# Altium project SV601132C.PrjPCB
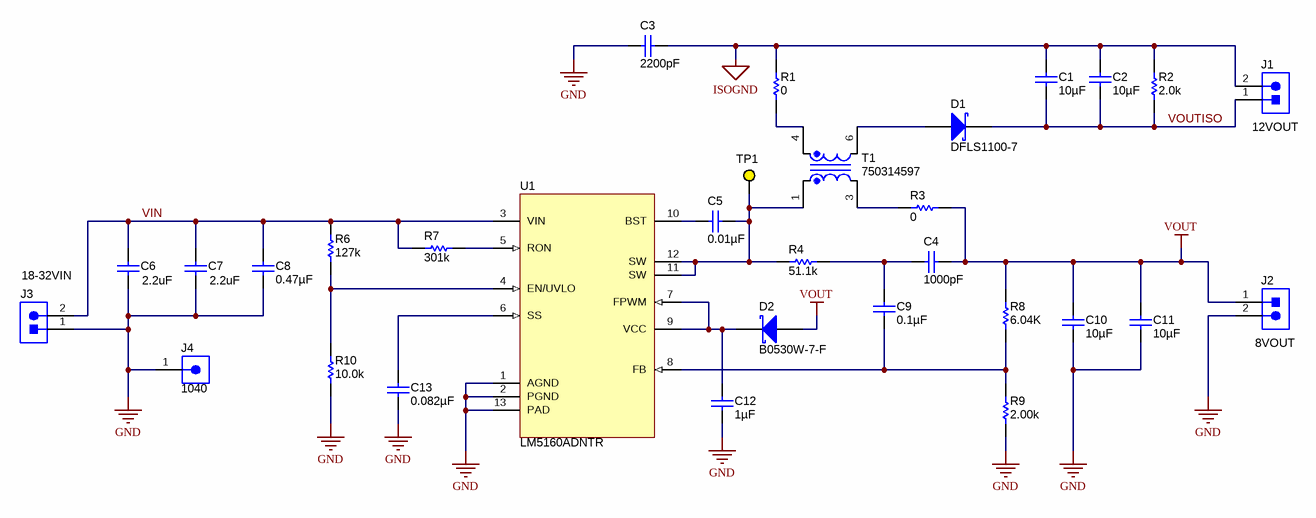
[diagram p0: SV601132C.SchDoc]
CopyrightYear: 2014; PCB_Layout: a0413446; PCB_Rev: B; PRJ_Customer: Public Release; PRJ_Engineer: a0221128; PRJ_Number: SV601132; PRJ_Title: LM5160DNTFBKEVM; SCH_Rev: C; TechSupport: http://www.ti.com/support; TID: N/A
2 sheets, 47 parts. Net scope: global (net labels, ports and power ports of the same name join across sheets).
Board file: SV601132B.PcbDoc
Sheets:
  SV601132C.SchDoc
  SV601132C_HW.SchDoc

## Sheet SV601132C.SchDoc
size 431 x 279 mm; Date: Not shown in title block; ApprovedBy: Not shown in title block; CheckedBy: Not shown in title block; Author: Not shown in title block; CompanyName: Not shown in title block; Engineer: Not shown in title block; Organization: Not shown in title block; Address1: Not shown in title block; Address2: Not shown in title block; Address3: Not shown in title block; Address4: Not shown in title block; DocumentNumber: 1; Revision: Use project parameter SCH_Rev; SheetNumber: 1; SheetTotal: 2; PageSetup: Record=PageOptions¦CenterHorizontal=True¦CenterVertical=True¦PrintScale=0.62¦XCorrection=1.00¦YCorrection=1.00¦PrintKind=0¦BorderSize=5000000¦LeftOffset=0¦BottomOffset=0¦Orientation=2¦PaperLength=1000¦PaperWidth=1000¦Scale=100¦PaperSource=7¦PrintQuality=600¦MediaType=1¦DitherType=10¦PaperKind=Letter¦PrintScaleMode=1

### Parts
C1  ValueDisplayed: 10µF  [1210]  (hidden comment: GRM32ER7YA106KA12L)
C2  ValueDisplayed: 10µF  [1210]  (hidden comment: GRM32ER7YA106KA12L)
C3  ValueDisplayed: 2200pF  [1812]  (hidden comment: C4532X7R3D222K130KA)
C4  ValueDisplayed: 1000pF  [0603]  (hidden comment: GRM188R71C102KA01D)
C5  ValueDisplayed: 0.01µF  [0603]  (hidden comment: GRM188R71C103KA01D)
C6  value 2.2uF  [1210]  (hidden comment: GRM32ER72A225KA35K)
C7  value 2.2uF  [1210]  (hidden comment: GRM32ER72A225KA35K)
C8  ValueDisplayed: 0.47µF  [0805_HV]  (hidden comment: GRM21BR72A474KA73L)
C9  ValueDisplayed: 0.1µF  [0603]  (hidden comment: 06033C104JAT2A)
C10  ValueDisplayed: 10µF  [1210]  (hidden comment: GRM32ER7YA106KA12L)
C11  ValueDisplayed: 10µF  [1210]  (hidden comment: GRM32ER7YA106KA12L)
C12  ValueDisplayed: 1µF  [0603]  (hidden comment: C1608X7R1C105K080AC)
C13  ValueDisplayed: 0.082µF  [0603]  (hidden comment: GRM188R71C823KA01D)
D1  DFLS1100-7  [powerDI123]
D2  B0530W-7-F  [SOD-123]
J1  ED555/2DS  [TERM_BLK_ED555-2DS]  (value not drawn)
J2  ED555/2DS  [TERM_BLK_ED555-2DS]  (value not drawn)
J3  ED555/2DS  [TERM_BLK_ED555-2DS]  (value not drawn)
J4  1040  [CONN_1040]
R1  value 0  [0805_HV]  (hidden comment: CRCW08050000Z0EA)
R2  value 2.0k  [0805_HV]  (hidden comment: CRCW08052K00JNEA)
R3  value 0  [0805_HV]  (hidden comment: CRCW08050000Z0EA)
R4  value 51.1k  [0603]  (hidden comment: RC0603FR-0751K1L)
R6  value 127k  [0603]  (hidden comment: RC0603FR-07127KL)
R7  value 301k  [0603]  (hidden comment: CRCW0603301KFKEA)
R8  value 6.04K  [0603]  (hidden comment: CRCW06036K04FKEA)
R9  value 2.00k  [0603]  (hidden comment: CRCW06032K00FKEA)
R10  value 10.0k  [0603]  (hidden comment: CRCW060310K0FKEA)
T1  750314597  [WURTH_750314597]
TP1  5014  [Keystone5014]  (value not drawn)
U1  LM5160ADNTR  [DNT0012B]

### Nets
GND: C3.1 C6.2 C7.2 C8.2 C10.2 C11.2 C12.2 C13.2 J2.2 J3.1 J4.1 R9.1 R10.1 U1.1(AGND) U1.2(PGND) U1.13(PAD)
ISOGND: C1.1 C2.1 C3.2 J1.2 R1.2 R2.2
VOUT: C4.2 C10.1 C11.1 D2.2(A) J2.1 R3.1 R8.2
VIN: C6.1 C7.1 C8.1 J3.2 R6.2 R7.2 U1.3(VIN)
VOUTISO: C1.2 C2.2 D1.1(K) J1.1 R2.1
NetC4_1: C4.1 C9.1 R4.2
NetC5_1: C5.1 R4.1 T1.1 TP1.1 U1.11(SW) U1.12(SW)
NetC5_2: C5.2 U1.10(BST)
NetC9_2: C9.2 R8.1 R9.2 U1.8(FB)
NetC12_1: C12.1 D2.1(K) U1.7(FPWM) U1.9(VCC)
NetC13_1: C13.1 U1.6(SS)
NetD1_2: D1.2(A) T1.6
NetR1_1: R1.1 T1.4
NetR3_2: R3.2 T1.3
NetR6_1: R6.1 R10.2 U1.4(EN/UVLO)
NetR7_1: R7.1 U1.5(RON)

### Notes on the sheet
- (near J1) 12VOUT
- (near J3) 18-32VIN
- (near J2) 8VOUT

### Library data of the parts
C1 C2 C10 C11 = GRM32ER7YA106KA12L: CAP, CERM, 10uF, 35V, +/-10%, X7R, 1210; Manufacturer: MuRata; Polarized: N; CompType: Capacitor; U/M: EA; Cap_F: 0.00001; Tolerance_%: 10; Value1: Unknown; VDC_V: 35; TaMin_C: -55; TaMax_C: 125
C3 = C4532X7R3D222K: CAP, CERM, 2200pF, 2000V, +/-10%, X7R, 1812; Manufacturer: TDK; Polarized: N; CompType: Capacitor; U/M: EA; Cap_F: 0.0000000022; Tolerance_%: 10; Value1: Unknown; VDC_V: 2000; TaMin_C: -55; TaMax_C: 125
C4 = GRM188R71C102KA01D: CAP, CERM, 1000pF, 16V, +/-10%, X7R, 0603; Manufacturer: MuRata; Polarized: N; CompType: Capacitor; U/M: EA; Cap_F: 0.000000001; Tolerance_%: 10; Value1: Unknown; VDC_V: 16; TaMin_C: -55; TaMax_C: 125
C5 = GRM188R71C103KA01D: CAP, CERM, 0.01uF, 16V, +/-10%, X7R, 0603; Manufacturer: MuRata; Polarized: N; CompType: Capacitor; U/M: EA; Cap_F: 0.00000001; Tolerance_%: 10; Value1: Unknown; VDC_V: 16; TaMin_C: -55; TaMax_C: 125
C6 C7 = Capacitor: CAP, CERM, 2.2uF, 100V, X7R, 10%, 1210; Manufacturer: Murata; Polarized: N; U/M: EA
C8 = GRM21BR72A474KA73L: CAP, CERM, 0.47uF, 100V, +/-10%, X7R, 0805; Manufacturer: MuRata; Polarized: N; CompType: Capacitor; U/M: EA; Cap_F: 0.00000047; Tolerance_%: 10; Value1: Unknown; VDC_V: 100; TaMin_C: -55; TaMax_C: 125; Cap_Case: 0805
C9 = 06033C104JAT2A: CAP, CERM, 0.1uF, 25V, +/-5%, X7R, 0603; Manufacturer: AVX; Polarized: N; CompType: Capacitor; U/M: EA; Cap_F: 0.0000001; Tolerance_%: 5; ESR_Ohm: 0.05; Value1: 0.05 ohm; VDC_V: 25; TaMin_C: -55; TaMax_C: 125
C12 = C1608X7R1C105K080AC: CAP, CERM, 1 µF, 16 V, +/- 10%, X7R, 0603; Manufacturer: TDK; Polarized: N; CompType: Capacitor; Value: 1uF; U/M: EA; Cap_F: 0.000001; Tolerance_%: 10; ESR_ohm: 0.0057; Value1: 0.0057 ohm; VDC_V: 16; Value2: 16V; TaMin_C: -55; TaMax_C: 125; AEC Category: Q200
C13 = GRM188R71C823KA01D: CAP, CERM, 0.082uF, 16V, +/-10%, X7R, 0603; Manufacturer: MuRata; Polarized: N; CompType: Capacitor; U/M: EA; Cap_F: 0.000000082; Tolerance_%: 10; Value1: Unknown; VDC_V: 16; TaMin_C: -55; TaMax_C: 125
D1 = DFLS1100-7: Diode, Schottky, 100V, 1A, PowerDI123; Manufacturer: Diodes Inc.; U/M: EA; Vf_V: 0.77; Value2: 0.77V; Io_A: 1; Vr_V: 100; TJmax_C: 175; RJC_CperW: 7
D2 = B0530W-7-F: Diode, Schottky, 30V, 0.5A, SOD-123; Manufacturer: Diodes Inc.; U/M: EA; Vf_V: 0.43; Value2: 0.43V; Io_A: 0.5; Vr_V: 30; TJmax_C: 125; RJC_CperW: 244
J1-J3 = ED555/2DS: Terminal Block, 6A, 3.5mm Pitch, 2-Pos, TH; Manufacturer: On-Shore Technology; SymbolCreator: a0412235; CompType: Connector; U/M: EA
J4 = 1040: TEST POINT SLOTTED .118", TH; Manufacturer: Keystone; SymbolCreator: a0412235; CompType: Test Point Loop; U/M: EA
R1 R3 = CRCW08050000Z0EA: RES, 0 ohm, 5%, 0.125W, 0805; Manufacturer: Vishay-Dale; CompType: Resistor; Value_Code: 0000; Tolerance_%: 5; Power_W: 0.125; VDC_V: 150; TempCo: 200 ppm/C; EIA_Code: E24; U/M: EA
R2 = CRCW08052K00JNEA: RES, 2.0k ohm, 5%, 0.125W, 0805; Manufacturer: Vishay-Dale; CompType: Resistor; Res_ohm: 2000; Value_Code: 2k00; Tolerance_%: 5; Power_W: 0.125; VDC_V: 150; TempCo: 200 ppm/C; EIA_Code: E24; U/M: EA
R4 = RC0603FR-0751K1L: RES, 51.1k ohm, 1%, 0.1W, 0603; Manufacturer: Yageo America; CompType: Resistor; U/M: EA; Res_ohm: 51100; Value_Code: 51k1; Tolerance_%: 1; Power_W: 0.1; VDC_V: 150; TempCo: 200 ppm/C; EIA_Code: E96
R6 = RC0603FR-07127KL: RES, 127k ohm, 1%, 0.1W, 0603; Manufacturer: Yageo America; CompType: Resistor; Res_ohm: 127000; Tolerance_%: 1; Power_W: 0.1; VDC_V: 150; TempCo: 200 ppm/C; EIA_Code: E96; U/M: EA
R7 = CRCW0603301KFKEA: RES, 301k ohm, 1%, 0.1W, 0603; Manufacturer: Vishay-Dale; CompType: Resistor; Res_ohm: 301000; Tolerance_%: 1; Power_W: 0.1; VDC_V: 75; TempCo: 100 ppm/C; EIA_Code: E96; U/M: EA
R8 = CRCW06036K04FKEA: RES, 6.04k ohm, 1%, 0.1W, 0603; Manufacturer: Vishay-Dale; CompType: Resistor; Res_ohm: 6040; Value_Code: 6k04; Tolerance_%: 1; Power_W: 0.1; VDC_V: 75; TempCo: 100 ppm/C; EIA_Code: E96; U/M: EA
R9 = CRCW06032K00FKEA: RES, 2.00k ohm, 1%, 0.1W, 0603; Manufacturer: Vishay-Dale; CompType: Resistor; Res_ohm: 2000; Value_Code: 2k00; Tolerance_%: 1; Power_W: 0.1; VDC_V: 75; TempCo: 100 ppm/C; EIA_Code: E96; U/M: EA
R10 = CRCW060310K0FKEA: RES, 10.0k ohm, 1%, 0.1W, 0603; Manufacturer: Vishay-Dale; CompType: Resistor; Res_ohm: 10000; Value_Code: 10k0; Tolerance_%: 1; Power_W: 0.1; VDC_V: 75; TempCo: 100 ppm/C; EIA_Code: E96; U/M: EA
T1 = 750314597: Transformer, 60uH, SMT; Manufacturer: Wurth Elektronik eiSos; SymbolCreator: a0799628; DCR_Ohm: 0.071; LeakageL: 0.6uH; U/M: EA
TP1 = 5014: Test Point, Multipurpose, Yellow, TH; Manufacturer: Keystone; CompType: Test Point Loop; U/M: EA
U1 = LM5160ADNTR: Wide Input 65V, 1.5A Synchronous Step-Down DC-DC Converter, DNT0012B; Alternate PartNumber: LM5160ADNTT; Manufacturer: Texas Instruments; SymbolCreator: a0411947; CompType: IC; U/M: EA

## Sheet SV601132C_HW.SchDoc
size 431 x 279 mm; Date: Not shown in title block; ApprovedBy: Not shown in title block; CheckedBy: Not shown in title block; Author: Not shown in title block; CompanyName: Not shown in title block; Engineer: Not shown in title block; Organization: Not shown in title block; Address1: Not shown in title block; Address2: Not shown in title block; Address3: Not shown in title block; Address4: Not shown in title block; DocumentNumber: 2; Revision: Use project parameter SCH_Rev; SheetNumber: 2; SheetTotal: 2; PageSetup: Record=PageOptions¦CenterHorizontal=True¦CenterVertical=True¦PrintScale=1.00¦XCorrection=1.00¦YCorrection=1.00¦PrintKind=0¦BorderSize=5000000¦LeftOffset=0¦BottomOffset=0¦Orientation=2¦PaperLength=1000¦PaperWidth=1000¦Scale=100¦PaperSource=15¦PrintQuality=600¦MediaType=1¦DitherType=10¦PaperKind=Letter¦PrintScaleMode=1
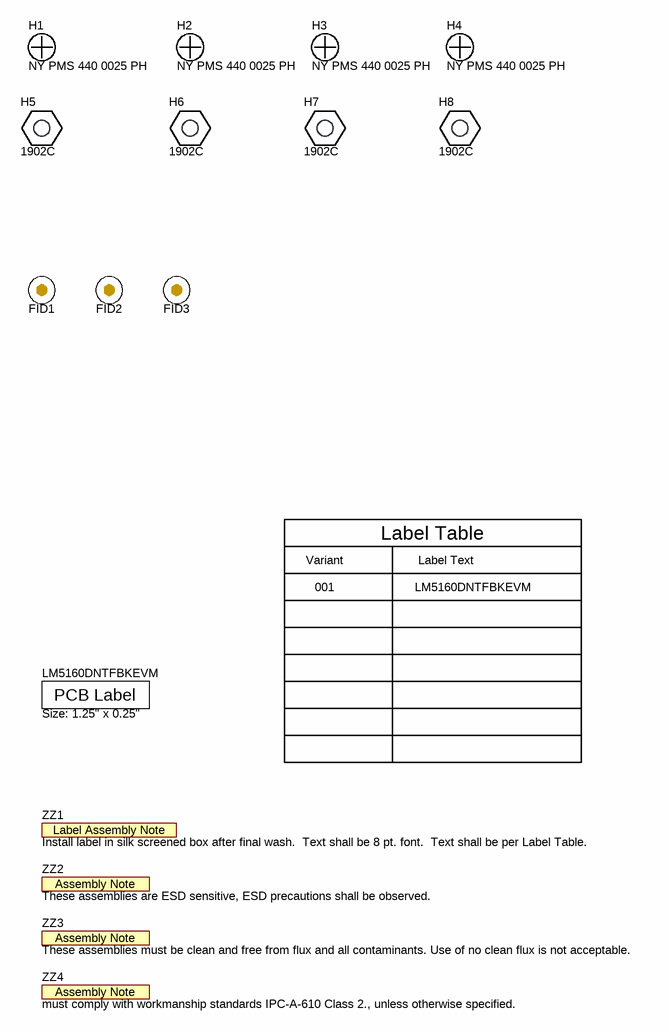
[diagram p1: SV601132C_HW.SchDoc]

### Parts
FID1  Fiducial  [Fiducial10-30]  (value not drawn)
FID2  Fiducial  [Fiducial10-30]  (value not drawn)
FID3  Fiducial  [Fiducial10-30]  (value not drawn)
H1  NY PMS 440 0025 PH  [NY PMS 440 0025 PH]
H2  NY PMS 440 0025 PH  [NY PMS 440 0025 PH]
H3  NY PMS 440 0025 PH  [NY PMS 440 0025 PH]
H4  NY PMS 440 0025 PH  [NY PMS 440 0025 PH]
H5  1902C  [Keystone_1902C]
H6  1902C  [Keystone_1902C]
H7  1902C  [Keystone_1902C]
H8  1902C  [Keystone_1902C]
LM5160DNTFBKEVM  Size: 1.25" x 0.25"  [Label_1250x250]
ZZ1  Install label in silk screened box after final wash.  Text shall be 8 pt. font.  Text shall be per Label Table.  [AssemblyNoteLabel]  (no BOM)
ZZ2  These assemblies are ESD sensitive, ESD precautions shall be observed.  [AssemblyNote]  (no BOM)
ZZ3  These assemblies must be clean and free from flux and all contaminants. Use of no clean flux is not acceptable.  [AssemblyNote]  (no BOM)
ZZ4  must comply with workmanship standards IPC-A-610 Class 2., unless otherwise specified.  [AssemblyNote]  (no BOM)

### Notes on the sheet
- Variant
- Label Table
- Label Text
- 001
- LM5160DNTFBKEVM

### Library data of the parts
FID1-FID3 = Fiducial: Fiducial mark.  There is nothing to buy or mount.; SymbolCreator: codlsc
H1-H4 = NY PMS 440 0025 PH: Machine Screw, Round, #4-40 x 1/4, Nylon, Philips panhead; Manufacturer: B&F Fastener Supply; CompType: Hardware; SymbolCreator: codlsc; U/M: EA
H5-H8 = 1902C: Standoff, Hex, 0.5"L #4-40 Nylon; Manufacturer: Keystone; CompType: Hardware; SymbolCreator: a0412235
LM5160DNTFBKEVM = THT-13-457-10: Thermal Transfer Printable Labels, 1.250" W x 0.250" H - 10,000 per roll; CompType: Label
ZZ1 = AssemblyNoteLabel: SymbolCreator: a0412235
ZZ2-ZZ4 = AssemblyNote: SymbolCreator: codlsc

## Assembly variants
001: not fitted FID1 FID2 FID3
